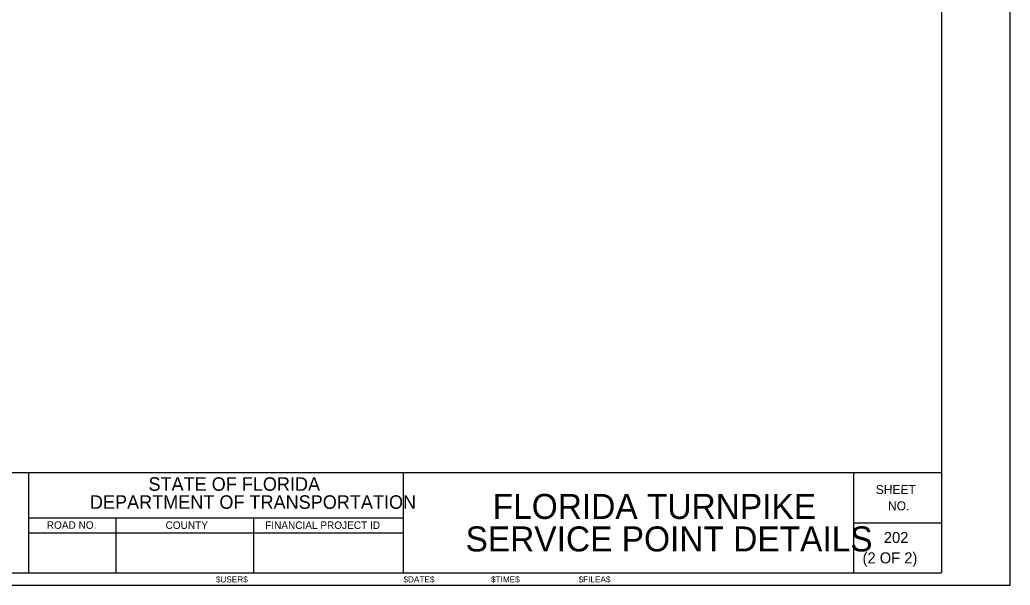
# Model space of a CAD drawing. Extents: x 359576 to 360896, y 1607020 to 1607868.
# Drawn here: x 360262 to 360896, y 1607020 to 1607381 of the extents above; entities that cross this region are included whole.
import ezdxf

# ---------------------------------------------------------------- set-up
doc = ezdxf.new("R2010")
doc.units = 0
for name, color, linetype in [('PlotBorder_dp', 7, 'Continuous'), ('SheetBorder_dp', 7, 'Continuous'), ('SheetLines_dp', 7, 'Continuous'), ('TextLabel', 7, 'Continuous'), ('TextMinor', 7, 'Continuous'), ('TextMisc', 7, 'Continuous')]:
    doc.layers.add(name, color=color, linetype=linetype)

msp = doc.modelspace()

# ---------------------------------------------------------------- linework, layer by layer
at = {"layer": 'PlotBorder_dp'}
msp.add_lwpolyline([(359575.91, 1607019.59), (360895.91, 1607019.59), (360895.91, 1607867.59), (359575.91, 1607867.59)], close=True, dxfattribs=at)
at = {"layer": 'SheetBorder_dp'}
for p, q in [((360851.91, 1607859.59), (360851.91, 1607027.59)), ((359619.91, 1607091.59), (360851.91, 1607091.59)), ((359619.91, 1607027.59), (360851.91, 1607027.59))]:
    msp.add_line(p, q, dxfattribs=at)
at = {"layer": 'SheetLines_dp'}
for p, q in [((360267.91, 1607091.59), (360267.91, 1607027.59)), ((360507.91, 1607027.59), (360507.91, 1607091.59)), ((360795.91, 1607027.59), (360795.91, 1607091.59)), ((360267.91, 1607062.79), (360507.91, 1607062.79)), ((360323.91, 1607062.79), (360323.91, 1607027.59)), ((360411.91, 1607062.79), (360411.91, 1607027.59)), ((360795.91, 1607059.59), (360851.91, 1607059.59)), ((360267.91, 1607053.19), (360507.91, 1607053.19))]:
    msp.add_line(p, q, dxfattribs=at)

# ---------------------------------------------------------------- texts
at = {"layer": 'TextLabel'}
for s, p in [('202', (360815.1, 1607046.59)), ('(2 OF 2)', (360801.49, 1607033.55))]:
    msp.add_text(s, height=7.04, dxfattribs=at).set_placement(p)
at = {"layer": 'TextMinor'}
for s, p in [('$USER$', (360387.83, 1607021.35)), ('$FILEA$', (360619.83, 1607021.35))]:
    msp.add_text(s, height=3.92, dxfattribs=at).set_placement(p)
for s, p in [('$DATE$', (360507.83, 1607021.35)), ('$TIME$', (360563.83, 1607021.35))]:
    msp.add_text(s, height=3.92, rotation=360, dxfattribs=at).set_placement(p)
at = {"layer": 'TextMisc'}
for s, height, p in [('STATE OF FLORIDA', 8.64, (360344.71, 1607079.99)), ('DEPARTMENT OF TRANSPORTATION', 8.64, (360307.27, 1607068.47)), ('    FLORIDA TURNPIKE    ', 15.9998, (360541.13, 1607061.99)), ('ROAD NO.', 4.8, (360279.67, 1607055.67)), ('COUNTY', 4.8, (360355.67, 1607055.59)), ('FINANCIAL PROJECT ID', 4.8, (360419.35, 1607055.59)), (' SERVICE POINT DETAILS  ', 15.9998, (360541.6, 1607041.19))]:
    msp.add_text(s, height=height, dxfattribs=at).set_placement(p)
for s, p in [('SHEET', (360809.91, 1607077.91)), ('NO.', (360817.75, 1607067.51))]:
    msp.add_text(s, height=5.76, rotation=359.86066, dxfattribs=at).set_placement(p)

doc.saveas('drawing.dxf')
